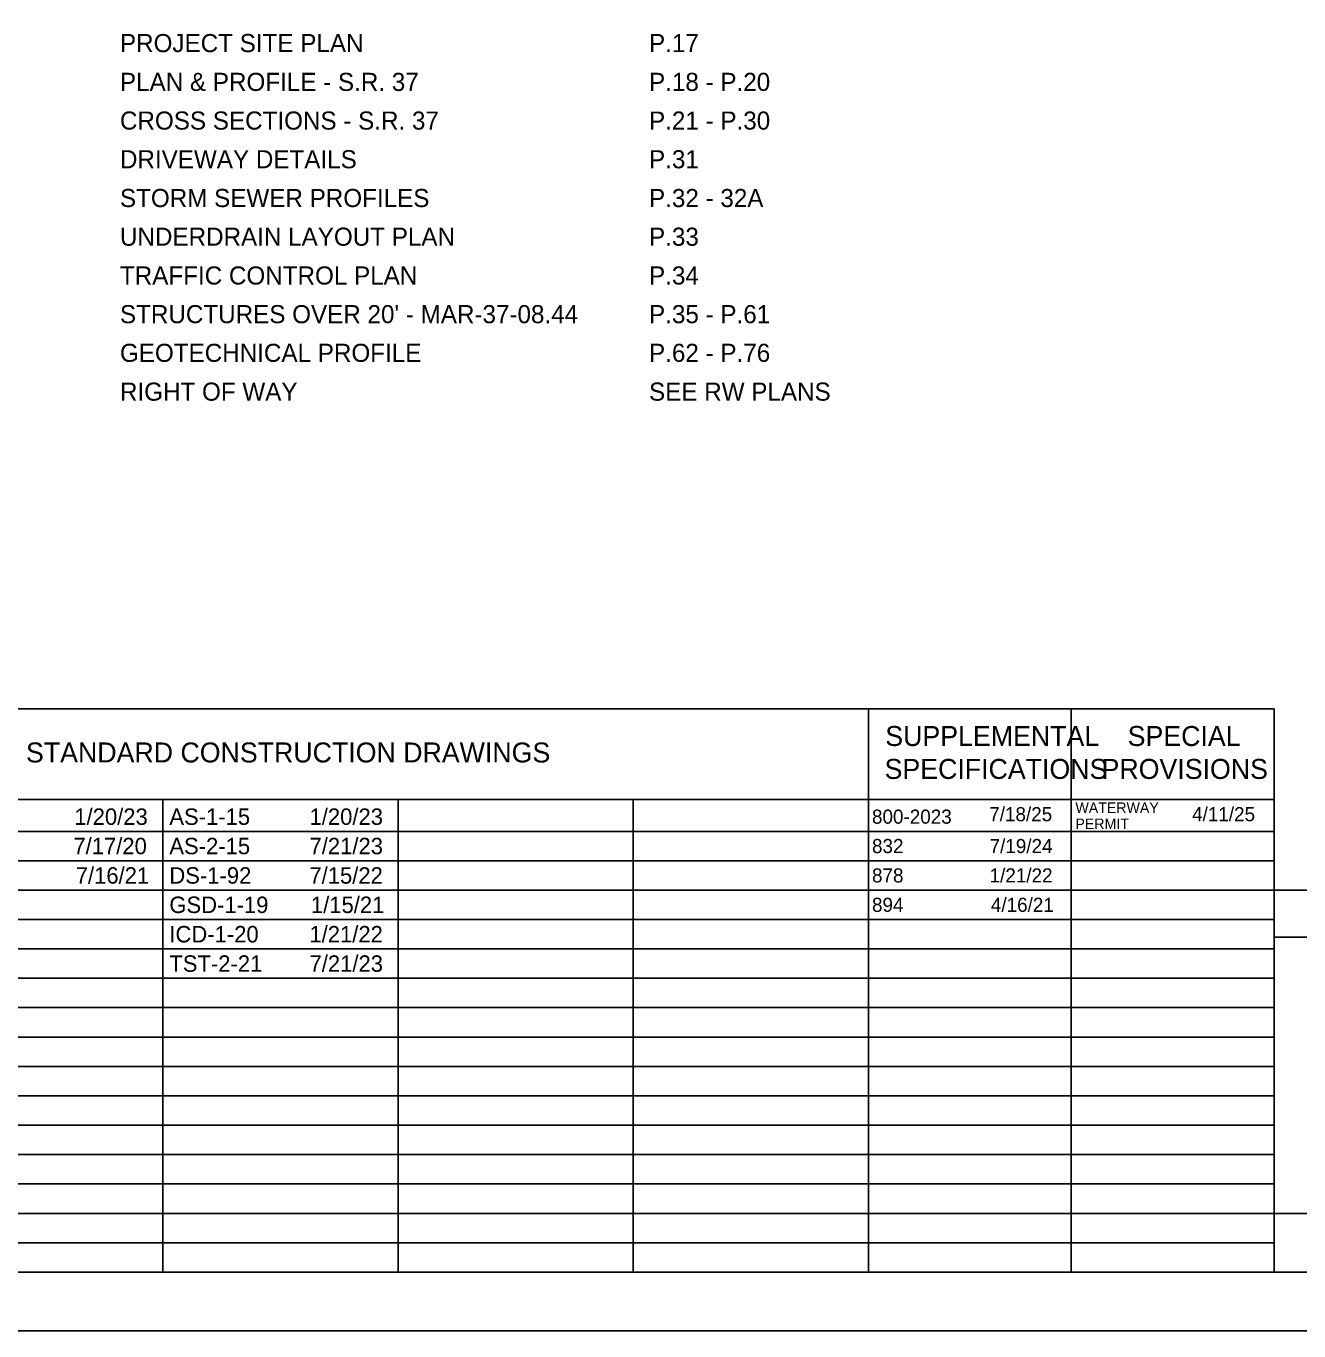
# Model space of a CAD drawing. Extents: x 0 to 34, y 0 to 22.
# Drawn here: x 12.99 to 23.81, y 0 to 11.1 of the extents above; entities that cross this region are included whole.
import ezdxf

# ---------------------------------------------------------------- set-up
doc = ezdxf.new("R2010")
doc.units = 0
for name, color, linetype in [('GM_X_County', 7, 'Continuous'), ('GM_X_Minor_Lake', 7, 'Continuous'), ('GM_X_Minor_Lake_Text', 7, 'Continuous'), ('GM_X_Minor_River_Text', 7, 'Continuous')]:
    doc.layers.add(name, color=color, linetype=linetype)

msp = doc.modelspace()

# ---------------------------------------------------------------- linework, layer by layer
at = {"layer": 'GM_X_County'}
msp.add_lwpolyline([(0, 0), (34, 0), (34, 22), (0, 22)], close=True, dxfattribs=at)
at = {"layer": 'GM_X_Minor_Lake_Text'}
for p, q in [((10.15, 5.292), (23.6, 5.292)), ((20.15, 0.5), (20.15, 5.292)), ((21.875, 0.5), (21.875, 5.292)), ((23.6, 0.5), (23.6, 5.292)), ((10.15, 4.521), (23.6, 4.521)), ((14.15, 0.5), (14.15, 4.521)), ((16.15, 0.5), (16.15, 4.521)), ((18.15, 0.5), (18.15, 4.521)), ((10.15, 4.25), (23.6, 4.25)), ((10.15, 4), (23.6, 4)), ((10.15, 3.75), (23.6, 3.75)), ((23.6, 0.5), (23.6, 3.75)), ((23.6, 3.75), (26.4, 3.75)), ((10.15, 3.5), (23.6, 3.5)), ((23.6, 3.35), (26.4, 3.35)), ((10.15, 3.25), (23.6, 3.25)), ((10.15, 3), (23.6, 3)), ((10.15, 2.75), (23.6, 2.75)), ((10.15, 2.5), (23.6, 2.5)), ((10.15, 2.25), (23.6, 2.25)), ((10.15, 2), (23.6, 2)), ((10.15, 1.75), (23.6, 1.75)), ((10.15, 1.5), (23.6, 1.5)), ((10.15, 1.25), (23.6, 1.25)), ((10.15, 1), (23.6, 1)), ((10.15, 0.75), (23.6, 0.75)), ((23.6, 0.5), (26.4, 0.5))]:
    msp.add_line(p, q, dxfattribs=at)
msp.add_lwpolyline([(23.6, 0.5), (23.6, 1), (26.4, 1), (26.4, 0.5)], close=True, dxfattribs=at)
at = {"layer": 'GM_X_Minor_River_Text'}
msp.add_lwpolyline([(1.5, 21.5), (33.5, 21.5), (33.5, 0.5), (1.5, 0.5)], close=True, dxfattribs=at)

# ---------------------------------------------------------------- texts
at = {"layer": 'GM_X_Minor_Lake'}
for s, height, p in [('PROJECT SITE PLAN', 0.154, (13.785, 10.879)), ('P.17', 0.154, (18.284, 10.879)), ('PLAN & PROFILE - S.R. 37', 0.154, (13.785, 10.549)), ('P.18 - P.20', 0.154, (18.284, 10.549)), ('CROSS SECTIONS - S.R. 37', 0.154, (13.785, 10.22)), ('P.21 - P.30', 0.154, (18.284, 10.22)), ('DRIVEWAY DETAILS', 0.154, (13.785, 9.891)), ('P.31', 0.154, (18.284, 9.891)), ('STORM SEWER PROFILES', 0.154, (13.785, 9.561)), ('P.32 - 32A', 0.154, (18.284, 9.561)), ('UNDERDRAIN LAYOUT PLAN', 0.154, (13.785, 9.232)), ('P.33', 0.154, (18.284, 9.232)), ('TRAFFIC CONTROL PLAN', 0.154, (13.785, 8.902)), ('P.34', 0.154, (18.284, 8.902)), ("STRUCTURES OVER 20' - MAR-37-08.44", 0.154, (13.785, 8.573)), ('P.35 - P.61', 0.154, (18.284, 8.573)), ('GEOTECHNICAL PROFILE', 0.154, (13.785, 8.244)), ('P.62 - P.76', 0.154, (18.284, 8.244)), ('RIGHT OF WAY', 0.154, (13.785, 7.914)), ('SEE RW PLANS', 0.154, (18.284, 7.914)), ('SUPPLEMENTAL', 0.17, (20.293, 4.976)), ('SPECIAL', 0.17, (22.354, 4.976)), ('STANDARD CONSTRUCTION DRAWINGS', 0.17, (12.986, 4.836)), ('SPECIFICATIONS', 0.17, (20.287, 4.696)), ('PROVISIONS', 0.17, (22.132, 4.696)), ('1/20/23', 0.14, (13.397, 4.305)), ('AS-1-15', 0.14, (14.205, 4.305)), ('1/20/23', 0.14, (15.397, 4.305)), ('7/18/25', 0.12, (21.177, 4.336)), ('WATERWAY', 0.09, (21.91, 4.406)), ('4/11/25', 0.12, (22.902, 4.336)), ('800-2023', 0.12, (20.18, 4.315)), ('PERMIT', 0.09, (21.91, 4.269)), ('7/17/20', 0.14, (13.389, 4.055)), ('AS-2-15', 0.14, (14.205, 4.055)), ('7/21/23', 0.14, (15.397, 4.055)), ('832', 0.12, (20.18, 4.065)), ('7/19/24', 0.12, (21.18, 4.065)), ('7/16/21', 0.14, (13.409, 3.805)), ('DS-1-92', 0.14, (14.205, 3.805)), ('7/15/22', 0.14, (15.396, 3.805)), ('878', 0.12, (20.18, 3.815)), ('1/21/22', 0.12, (21.18, 3.815)), ('GSD-1-19', 0.14, (14.205, 3.555)), ('1/15/21', 0.14, (15.409, 3.555)), ('894', 0.12, (20.18, 3.565)), ('4/16/21', 0.12, (21.191, 3.565)), ('ICD-1-20', 0.14, (14.205, 3.305)), ('1/21/22', 0.14, (15.396, 3.305)), ('TST-2-21', 0.14, (14.205, 3.055)), ('7/21/23', 0.14, (15.397, 3.055))]:
    msp.add_text(s, height=height, dxfattribs=at).set_placement(p)

doc.saveas('drawing.dxf')
